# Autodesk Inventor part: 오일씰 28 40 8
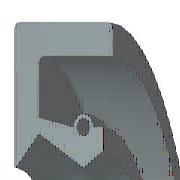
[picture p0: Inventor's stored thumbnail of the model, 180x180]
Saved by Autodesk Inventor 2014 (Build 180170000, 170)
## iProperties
IsCustomPart: 1
Created: 2012-02
Part Number: 오일씰 28 40 8
Material: 고무
Description: Oil-seal
Document SubType Name: Modeling
Standard: KS B 2804
Designer: mduedu
Standards Organization: KS
Language: en-US
Size Designation: D - 28 40 8
Categories: <MemberInstance><Categories><Category DisplayName="Shaft Parts" InternalName="7f7aeb1f-a693-4053-b835-cee3144e0d98" Mnemonic="SHFT"><Category DisplayName="Seali
Density: 0.93 g/cm^3
Mass: 2.83894 g
Surface Area: 40.7521 cm^2
Volume: 3.05262 cm^3
Appearance: Rubber - Black - Version 1.1
Author: mduedu
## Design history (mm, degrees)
revolve "Body" stored, may be unused: angle "d17" = 90 deg
revolve "Spring1" stored, may be unused: angle "d18" = 90 deg
body "Solid1"
sketch "Sketch1"
  geometry: L1 (0, 20)-(8, 20); L2 (8, 18.25)-(1.75, 18.25); L3 (1.75, 15.75)-(4.9, 14); L4 (4.9, 14)-(0, 14); L5 (0, 0)-(9.586, 0) reference; L6 (4.9, 14)-(6.3, 14.875); L7 (0, 18)-(0, -3) reference; L8 (-1.941, 0)-(11.507, 0) reference; L9 (4.2, 16.1)-(1.75, 16.71); L10 (1.75, 16.71)-(1.75, 18.25); L11 (0, 20)-(0, 14.088); L12 (4.9, 14)-(0, 14); L13 (1.75, 15.75)-(0.152, 14.028); L14 (8, 20)-(8, 18.25); L15 (5.6, 16.1)-(6.3, 16.1); L16 (6.3, 16.1)-(6.3, 14.875); C1 r 0.455 at (4.9, 16.1); A1 r 0.7 centre (4.9, 16.1) between (5.6, 16.1) and (4.2, 16.1); A2 r 0.088 centre (0.087, 14.088) between (0, 14.088) and (0.152, 14.028); 1 further point
  constraints: 28 end point, 5 horizontal alignment, 5 point on line, 4 point on circle, 4 vertical alignment, 3 centre point, 3 tangent, 2 collinear, 2 horizontal, 2 perpendicular, 1 coincident, 1 parallel
  dimensions: "d0" = 40 diameter of L1 L5 (= SD2); "d1" = 1.75 distance of L1.end L2.start (= SD); "d2" = 0.91 diameter of C1 (= SPDI); "d3" = 1.4 diameter of A1 (= SPDA); "d4" = 28 diameter of L3.end L5 (= NND); "d5" = 31.5 diameter of L3.start L5 (= TKDM); "d7" = 33.42 diameter of L9.end L5 (= TKDM + 0.24 x SWDT); "d8" = 1.75 distance between parallel lines of L11 L10 (= SD); "d9" = 4.9 distance from line of L11 C1.centre (= SPDST); "d10" = 32.2 diameter of C1.centre L5 (= HLDM); "d11" = 0.0875 radius of A2 (= 0.25 x LAB); "d12" = 6.3 distance between parallel lines of L11 L16 (= SDI); "d13" = 29.75 diameter of L6.end L5 (= ABDM); "d14" = 8 distance from line of L11 L1.end (= SWDT)
fillet "Fillet1" dims "d6" = 0.4 (= RR)
other parameters: "SD2" = 40 [user parameter; used in 1 equation term], "SWDT" = 8 [user parameter; used in 2 equation terms], "RR" = 0.4 [user parameter; used in 1 equation term], "SD" = 1.75 [user parameter; used in 2 equation terms], "NND" = 28 [user parameter; used in 1 equation term], "SPDA" = 1.4 [user parameter; used in 1 equation term], "SPDI" = 0.91 [user parameter; used in 1 equation term], "TKDM" = 31.5 [user parameter; used in 2 equation terms], "HLDM" = 32.2 [user parameter; used in 1 equation term], "ABDM" = 29.75 [user parameter; used in 1 equation term], "SDI" = 6.3 [user parameter; used in 1 equation term], "SPDST" = 4.9 [user parameter; used in 1 equation term], "LAB" = 0.35 [user parameter; used in 1 equation term], "d15" = 0, "d16" = 0, "d19" = 0
